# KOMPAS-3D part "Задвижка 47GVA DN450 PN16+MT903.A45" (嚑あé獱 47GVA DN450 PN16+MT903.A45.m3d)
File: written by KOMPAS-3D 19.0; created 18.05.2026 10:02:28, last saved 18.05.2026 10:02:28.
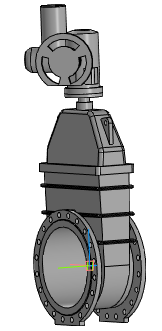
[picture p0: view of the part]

Document properties: Автор: Энергия; Полное имя файла: ..\Задвижка 47GVA DN50_DN1000+MT903.A\Задвижка 47GVA DN450 PN16+MT903.A45.a3d

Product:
- Part/product: Задвижка 47GVA DN450 PN16+MT903.A45
    Масса: 850.598
  - Body: Электропривод МТ903.А45 без блока управления
      Масса: 175.721
  - Body: Задвижка 47GVA DN450 PN16 без исполнительного механизма
      Масса: 674.877

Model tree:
1. Операция без истории:1
2. Операция без истории:2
